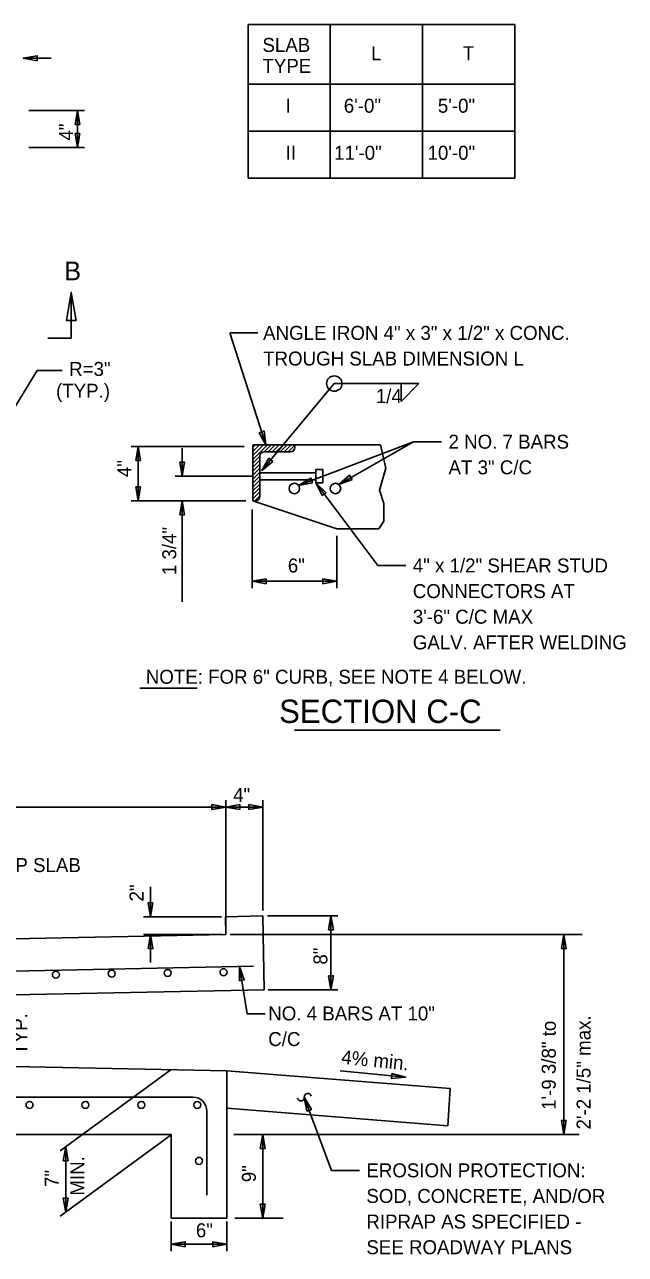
# Model space of a CAD drawing. Extents: x 12.4 to 21.1, y 6 to 16.1.
# Drawn here: x 16.66 to 19.23, y 10.77 to 16.05 of the extents above; entities that cross this region are included whole.
import ezdxf

# ---------------------------------------------------------------- set-up
doc = ezdxf.new("R2010")
doc.units = 0
for name, color, linetype in [('V7_LEVEL_1', 7, 'Continuous'), ('V7_LEVEL_10', 7, 'Continuous'), ('V7_LEVEL_12', 7, 'Continuous'), ('V7_LEVEL_13', 7, 'Continuous'), ('V7_LEVEL_35', 7, 'Continuous'), ('V7_LEVEL_44', 7, 'Continuous')]:
    doc.layers.add(name, color=color, linetype=linetype)

msp = doc.modelspace()

# ---------------------------------------------------------------- linework, layer by layer
at = {"layer": 'V7_LEVEL_1'}
for p, q in [((18.1842, 14.2468), (17.6359, 14.2468)), ((17.6359, 14.2468), (17.6359, 14.0068)), ((17.8159, 14.2468), (17.6359, 14.2468)), ((17.6839, 14.2168), (17.7979, 14.2168)), ((17.8159, 14.2348), (17.8159, 14.2468)), ((17.6659, 14.0248), (17.6659, 14.1988)), ((17.6659, 14.1268), (17.9059, 14.1268)), ((17.6659, 14.0968), (17.9059, 14.0968)), ((17.9059, 14.1406), (17.9059, 14.083)), ((17.9059, 14.1406), (17.9359, 14.1406)), ((17.9359, 14.1406), (17.9359, 14.083)), ((17.9059, 14.083), (17.9359, 14.083)), ((17.6359, 14.0068), (17.9959, 13.8868)), ((17.6359, 14.0068), (17.6479, 14.0068)), ((18.177, 13.8868), (17.9959, 13.8868)), ((17.6788, 12.2244), (17.5189, 12.2212)), ((17.5204, 12.1444), (17.5189, 12.2212)), ((17.6852, 11.9076), (17.6788, 12.2244)), ((17.5204, 12.1444), (14.8004, 12.09)), ((17.6389, 12.0086), (15.0431, 11.9567)), ((17.6852, 11.9076), (15.0451, 11.8548)), ((17.5252, 11.5604), (15.0452, 11.61)), ((17.5252, 11.5604), (17.5252, 11.2804)), ((18.4823, 11.4837), (17.5252, 11.5604)), ((18.4727, 11.3239), (18.4823, 11.4837)), ((17.3791, 11.4467), (14.8852, 11.4467)), ((17.059, 11.4467), (16.819, 11.4467)), ((17.439, 11.3867), (17.439, 11.0266)), ((18.4727, 11.3239), (17.5252, 11.3999)), ((17.2852, 11.2868), (14.8052, 11.2868)), ((17.2852, 11.2868), (17.2852, 10.9268)), ((17.5252, 11.2868), (17.5252, 10.9268)), ((17.5252, 10.9268), (17.2852, 10.9268))]:
    msp.add_line(p, q, dxfattribs=at)
msp.add_lwpolyline([(18.1842, 14.2468), (18.2074, 14.1463), (18.1791, 14.0519), (18.1979, 13.9952), (18.1979, 13.9197), (18.177, 13.8868)], dxfattribs=at)
for centre, radius in [((17.8143, 14.0593), 0.0225), ((17.9907, 14.0593), 0.0225), ((16.7909, 11.9726), 0.015), ((17.0308, 11.9774), 0.015), ((17.2706, 11.9802), 0.015), ((17.5103, 11.9831), 0.015), ((16.6778, 11.4133), 0.015), ((16.9178, 11.4133), 0.015), ((17.1578, 11.4133), 0.015), ((17.3978, 11.4133), 0.015), ((17.4051, 11.1733), 0.015)]:
    msp.add_circle(centre, radius, dxfattribs=at)
for centre, radius, start, end in [((17.6839, 14.1988), 0.018, 90, 180), ((17.7979, 14.2348), 0.018, 270, 0), ((17.6479, 14.0248), 0.018, 270, 0), ((17.379, 11.3867), 0.06, 360, 90)]:
    msp.add_arc(centre, radius, start, end, dxfattribs=at)
at = {"layer": 'V7_LEVEL_10'}
for p, q in [((16.7708, 15.906), (16.6508, 15.906)), ((16.6752, 15.6816), (16.9136, 15.6816)), ((16.8836, 15.6816), (16.8731, 15.6216)), ((16.8941, 15.6216), (16.8836, 15.6816)), ((16.8836, 15.6816), (16.8836, 15.5232)), ((16.8731, 15.6216), (16.8941, 15.6216)), ((16.8941, 15.5832), (16.8731, 15.5832)), ((16.8731, 15.5832), (16.8836, 15.5232)), ((16.8836, 15.5232), (16.8941, 15.5832)), ((16.9136, 15.5232), (16.6752, 15.5232)), ((16.8572, 14.901), (16.8572, 14.7042)), ((16.8572, 14.7042), (16.7569, 14.7042)), ((17.6919, 14.2468), (17.5378, 14.7271)), ((17.6578, 14.7271), (17.5378, 14.7271)), ((18.3489, 14.5097), (18.2721, 14.4329)), ((18.2721, 14.4329), (18.2721, 14.5097)), ((17.6639, 14.2982), (17.6843, 14.3063)), ((17.6843, 14.3063), (17.6919, 14.2468)), ((17.6919, 14.2468), (17.6639, 14.2982)), ((17.8324, 14.0727), (18.3259, 14.2603)), ((18.0045, 14.0771), (18.3259, 14.2603)), ((18.4459, 14.2603), (18.3259, 14.2603)), ((17.5988, 14.2395), (17.1143, 14.2395)), ((17.1338, 14.1795), (17.1443, 14.2395)), ((17.1443, 14.2395), (17.1443, 14.0068)), ((17.1443, 14.2395), (17.1548, 14.1795)), ((17.3327, 14.1118), (17.3327, 14.2318)), ((17.1548, 14.1795), (17.1338, 14.1795)), ((17.3327, 14.1118), (17.3222, 14.1718)), ((17.3222, 14.1718), (17.3432, 14.1718)), ((17.3432, 14.1718), (17.3327, 14.1118)), ((17.6359, 14.1118), (17.3027, 14.1118)), ((17.1443, 14.0068), (17.1338, 14.0668)), ((17.1338, 14.0668), (17.1548, 14.0668)), ((17.1548, 14.0668), (17.1443, 14.0068)), ((17.9059, 14.083), (18.1727, 13.7289)), ((17.6059, 14.0068), (17.1143, 14.0068)), ((17.3327, 14.0068), (17.3222, 13.9468)), ((17.3327, 13.5723), (17.3327, 14.0068)), ((17.3432, 13.9468), (17.3327, 14.0068)), ((17.3222, 13.9468), (17.3432, 13.9468)), ((17.3222, 13.9468), (17.3432, 13.9468)), ((17.6336, 13.9695), (17.6336, 13.6313)), ((17.9959, 13.6313), (17.9959, 13.8568)), ((18.2927, 13.7289), (18.1727, 13.7289)), ((17.6936, 13.6718), (17.6336, 13.6613)), ((17.6936, 13.6508), (17.6936, 13.6718)), ((17.9959, 13.6613), (17.9359, 13.6718)), ((17.9359, 13.6718), (17.9359, 13.6508)), ((17.6336, 13.6613), (17.9959, 13.6613)), ((17.6336, 13.6613), (17.6936, 13.6508)), ((17.9359, 13.6508), (17.9959, 13.6613)), ((17.1514, 13.2025), (17.397, 13.2025)), ((17.5204, 12.6916), (17.5204, 12.7218)), ((17.5204, 12.168), (17.5204, 12.7218)), ((17.6788, 12.7218), (17.6788, 12.248)), ((14.7989, 12.6918), (17.5204, 12.6918)), ((17.4604, 12.7023), (17.5204, 12.6918)), ((17.4604, 12.6813), (17.4604, 12.7023)), ((17.5204, 12.6918), (17.4604, 12.6813)), ((17.5804, 12.7023), (17.5204, 12.6918)), ((17.5204, 12.6918), (17.5804, 12.6813)), ((17.5204, 12.6918), (17.6788, 12.6918)), ((17.5804, 12.6813), (17.5804, 12.7023)), ((17.6788, 12.6918), (17.6188, 12.7023)), ((17.6188, 12.7023), (17.6188, 12.6813)), ((17.6188, 12.6813), (17.6788, 12.6918)), ((17.197, 12.35), (17.197, 12.2212)), ((17.5024, 12.2212), (17.167, 12.2212)), ((17.6984, 12.2244), (18.0015, 12.2244)), ((17.961, 12.1644), (17.9715, 12.2244)), ((17.9715, 12.2244), (17.982, 12.1644)), ((17.9715, 12.2244), (17.9715, 11.9076)), ((17.504, 12.1444), (17.167, 12.1444)), ((17.197, 12.0244), (17.197, 12.1444)), ((17.5385, 12.1444), (19.05, 12.1444)), ((17.982, 12.1644), (17.961, 12.1644)), ((18.9709, 12.1444), (18.9709, 11.2868)), ((17.5791, 12.0074), (17.6125, 11.805)), ((17.982, 11.9676), (17.961, 11.9676)), ((17.961, 11.9676), (17.9715, 11.9076)), ((17.9715, 11.9076), (17.982, 11.9676)), ((18.0015, 11.9076), (17.7024, 11.9076)), ((17.6893, 11.805), (17.6125, 11.805)), ((17.2852, 11.5652), (16.809, 11.216)), ((18.2917, 11.532), (18.0109, 11.5604)), ((17.8569, 11.4468), (17.9734, 11.1327)), ((17.2852, 11.2852), (16.809, 10.936)), ((17.5552, 11.2868), (19.0365, 11.2868)), ((17.6784, 10.9268), (17.6784, 11.2868)), ((16.8332, 11.2337), (16.8332, 10.9537)), ((18.0934, 11.1327), (17.9734, 11.1327)), ((17.559, 10.9268), (17.7662, 10.9268)), ((17.2852, 10.9128), (17.2852, 10.7854)), ((17.5252, 10.9128), (17.5252, 10.7854)), ((17.2852, 10.8154), (17.5252, 10.8154))]:
    msp.add_line(p, q, dxfattribs=at)
for points in [[(16.7108, 15.8955), (16.6508, 15.906), (16.7108, 15.9165)], [(16.8782, 14.781), (16.8572, 14.901), (16.8362, 14.781)], [(17.7216, 14.1755), (17.6752, 14.1361), (17.7055, 14.1889)], [(17.8922, 14.0842), (17.8324, 14.0727), (17.8848, 14.1038)], [(18.0618, 14.0977), (18.0045, 14.0771), (18.0514, 14.1159)], [(17.9337, 14.0287), (17.9059, 14.083), (17.9504, 14.0414)], [(17.2075, 12.2812), (17.197, 12.2212), (17.1865, 12.2812)], [(17.1865, 12.0844), (17.197, 12.1444), (17.2075, 12.0844)], [(18.9604, 12.0844), (18.9709, 12.1444), (18.9814, 12.0844)], [(17.5785, 11.9465), (17.5791, 12.0074), (17.5992, 11.9499)], [(18.233, 11.5485), (18.2917, 11.532), (18.2309, 11.5276)], [(17.8679, 11.3868), (17.8569, 11.4468), (17.8876, 11.3941)], [(18.9814, 11.3468), (18.9709, 11.2868), (18.9604, 11.3468)], [(17.6679, 11.2268), (17.6784, 11.2868), (17.6889, 11.2268)], [(16.8227, 11.1737), (16.8332, 11.2337), (16.8437, 11.1737)], [(16.8437, 11.0137), (16.8332, 10.9537), (16.8227, 11.0137)], [(17.6889, 10.9868), (17.6784, 10.9268), (17.6679, 10.9868)], [(17.3452, 10.8049), (17.2852, 10.8154), (17.3452, 10.8259)], [(17.4652, 10.8259), (17.5252, 10.8154), (17.4652, 10.8049)]]:
    msp.add_lwpolyline(points, close=True, dxfattribs=at)
for points in [[(16.4445, 14.1304), (16.7101, 14.5657), (16.8177, 14.5657)], [(17.6752, 14.1361), (17.9857, 14.5097), (18.3489, 14.5097)]]:
    msp.add_lwpolyline(points, dxfattribs=at)
msp.add_circle((17.9857, 14.5097), 0.033, dxfattribs=at)
for centre, start, end in [((17.8718, 11.4482), 8.3056, 185.3613), ((17.842, 11.4453), 188.3056, 5.3613)]:
    msp.add_arc(centre, 0.015, start, end, dxfattribs=at)
at = {"layer": 'V7_LEVEL_13'}
for p, q in [((17.6159, 16.0505), (18.7598, 16.0505)), ((17.6159, 16.0505), (17.6159, 15.3908)), ((17.9674, 16.0505), (17.9674, 15.3908)), ((18.3636, 16.0505), (18.3636, 15.3908)), ((18.7598, 16.0505), (18.7598, 15.3908)), ((17.6159, 15.7944), (18.7598, 15.7944)), ((17.6159, 15.5926), (18.7598, 15.5926)), ((17.6159, 15.3908), (18.7598, 15.3908)), ((17.6159, 15.3908), (18.7598, 15.3908))]:
    msp.add_line(p, q, dxfattribs=at)
at = {"layer": 'V7_LEVEL_35'}
for p, q in [((17.6359, 14.2353), (17.6474, 14.2468)), ((17.6359, 14.2183), (17.6644, 14.2468)), ((17.6359, 14.2013), (17.6814, 14.2468)), ((17.6359, 14.1844), (17.6984, 14.2468)), ((17.6853, 14.2168), (17.7153, 14.2468)), ((17.7023, 14.2168), (17.7323, 14.2468)), ((17.7193, 14.2168), (17.7493, 14.2468)), ((17.7362, 14.2168), (17.7662, 14.2468)), ((17.7532, 14.2168), (17.7832, 14.2468)), ((17.7702, 14.2168), (17.8002, 14.2468)), ((17.7872, 14.2168), (17.8159, 14.2456)), ((17.8061, 14.2188), (17.8138, 14.2264)), ((17.6359, 14.1674), (17.6659, 14.1974)), ((17.6359, 14.1504), (17.6659, 14.1804)), ((17.6359, 14.1334), (17.6659, 14.1634)), ((17.6359, 14.1165), (17.6659, 14.1465)), ((17.6359, 14.0995), (17.6659, 14.1295)), ((17.6359, 14.0825), (17.6659, 14.1125)), ((17.6359, 14.0656), (17.6659, 14.0956)), ((17.6359, 14.0486), (17.6659, 14.0786)), ((17.6359, 14.0316), (17.6659, 14.0616)), ((17.6359, 14.0146), (17.6659, 14.0446)), ((17.6451, 14.0068), (17.6659, 14.0277))]:
    msp.add_line(p, q, dxfattribs=at)
at = {"layer": 'V7_LEVEL_44'}
msp.add_line((17.8145, 13.0225), (18.6973, 13.0225), dxfattribs=at)

# ---------------------------------------------------------------- texts
at = {"layer": 'V7_LEVEL_12'}
for s, rotation, p in [('4"', 90, (16.8651, 15.5526)), ('4"', 90, (17.1143, 14.1082)), ('1 3/4"', 90, (17.3077, 13.6874)), ('2"', 90, (17.167, 12.2867)), ('8"', 90, (17.9561, 12.0156)), ('TYP.', 90, (16.6683, 11.6291)), ('1\'-9 3/8" to', 90, (18.936, 11.3921)), ('2\'-2 1/5" max.', 90, (19.0854, 11.3081)), ('4% min.', 354.2183, (18.0136, 11.5902)), ('MIN.', 90, (16.9131, 11.0241)), ('9"', 90, (17.6493, 11.0817)), ('7"', 90, (16.8031, 11.0613))]:
    msp.add_text(s, height=0.06, rotation=rotation, dxfattribs=at).set_placement(p)
for s, height, p in [('B', 0.08, (16.8277, 14.9532)), ('ANGLE IRON 4" x 3" x 1/2" x CONC.', 0.06, (17.6802, 14.6972)), ('TROUGH SLAB DIMENSION L', 0.06, (17.6802, 14.5872)), ('R=3"', 0.06, (16.8479, 14.5424)), ('(TYP.)', 0.06, (16.7916, 14.4487)), ('1/4', 0.06, (18.164, 14.4259)), ('2 NO. 7 BARS', 0.06, (18.4758, 14.2302)), ('AT 3" C/C', 0.06, (18.4758, 14.1202)), ('6"', 0.06, (17.7863, 13.6989)), ('4" x 1/2" SHEAR STUD', 0.06, (18.3225, 13.6989)), ('CONNECTORS AT', 0.06, (18.3225, 13.5889)), ('3\'-6" C/C MAX', 0.06, (18.3225, 13.4789)), ('GALV. AFTER WELDING', 0.06, (18.3225, 13.3689)), ('NOTE: FOR 6" CURB, SEE NOTE 4 BELOW.', 0.06, (17.1768, 13.2212)), ('SECTION C-C', 0.1, (17.7489, 13.0531)), ('4"', 0.06, (17.5516, 12.7141)), ('TOP SLAB', 0.06, (16.5058, 12.4129)), ('NO. 4 BARS AT 10"', 0.06, (17.7023, 11.7761)), ('C/C', 0.06, (17.7023, 11.6661)), ('EROSION PROTECTION:', 0.06, (18.1233, 11.1027)), ('SOD, CONCRETE, AND/OR', 0.06, (18.1233, 10.9927)), ('RIPRAP AS SPECIFIED -', 0.06, (18.1233, 10.8827)), ('6"', 0.06, (17.3918, 10.8454)), ('SEE ROADWAY PLANS', 0.06, (18.1233, 10.7727))]:
    msp.add_text(s, height=height, dxfattribs=at).set_placement(p)
at = {"layer": 'V7_LEVEL_13'}
for s, p in [('SLAB', (17.6774, 15.9332)), ('L', (18.1433, 15.8974)), ('T', (18.537, 15.8974)), ('TYPE', (17.6774, 15.8432)), ('I', (17.7768, 15.6722)), ('6\'-0"', (18.0265, 15.6722)), ('5\'-0"', (18.4302, 15.6722)), ('II', (17.7768, 15.4704)), ('11\'-0"', (17.9849, 15.4704)), ('10\'-0"', (18.3858, 15.4704))]:
    msp.add_text(s, height=0.06, dxfattribs=at).set_placement(p)

doc.saveas('drawing.dxf')
